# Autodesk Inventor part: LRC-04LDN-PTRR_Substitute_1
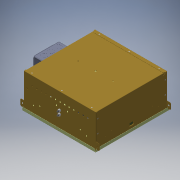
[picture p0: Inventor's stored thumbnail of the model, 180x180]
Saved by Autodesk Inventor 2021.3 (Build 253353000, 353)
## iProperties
Part Number: LRC-04LDN-PTRR_Substitute_1
Material: Generic
Document SubType Name: Modeling
Designer: JChurch
Manufacturer: Standard
Standards Organization: Custom
Density: 1 g/cm^3
Appearance: Smooth - Black
Author: JChurch
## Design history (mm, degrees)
derived "LRC-04LDN-PTRR.iam"
body "Solid9"
node "830520-00-00.ipt:1"
node "881088-00-00.iam:1::830140-00-00.ipt:1"
body "Solid10"
node "881088-00-00.iam:1::850014-00-00.iam:1::805044-00-00.ipt:1"
body "Solid11"
node "881088-00-00.iam:1::850014-00-00.iam:1::805174-00-00.ipt:1"
body "Solid12"
node "881088-00-00.iam:1::850014-00-00.iam:1::502055-00-00.ipt:1"
body "Solid13"
node "881088-00-00.iam:1::850014-00-00.iam:1::502055-00-00.ipt:2"
body "Solid14"
node "881088-00-00.iam:1::850014-00-00.iam:1::507032-00-00.ipt:1"
body "Solid15"
node "881088-00-00.iam:1::507000-00-00.ipt:1"
body "Solid16"
node "881088-00-00.iam:1::507000-00-00.ipt:2"
body "Solid17"
node "881088-00-00.iam:1::506002-00-00.ipt:1"
body "Solid18"
node "881088-00-00.iam:1::506002-00-00.ipt:2"
body "Solid19"
node "881088-00-00.iam:1::506002-00-00.ipt:3"
body "Solid20"
node "881088-00-00.iam:1::506002-00-00.ipt:4"
body "Solid21"
node "881088-00-00.iam:1::506002-00-00.ipt:5"
body "Solid22"
node "881088-00-00.iam:1::506002-00-00.ipt:6"
body "Solid23"
node "881088-00-00.iam:1::506002-00-00.ipt:7"
body "Solid24"
node "881088-00-00.iam:1::506002-00-00.ipt:8"
body "Solid25"
node "881088-00-00.iam:1::506002-00-00.ipt:9"
body "Solid26"
node "881088-00-00.iam:1::506002-00-00.ipt:10"
body "Solid27"
node "881088-00-00.iam:1::506002-00-00.ipt:11"
body "Solid28"
node "881088-00-00.iam:1::506002-00-00.ipt:12"
body "Solid29"
node "881088-00-00.iam:1::506002-00-00.ipt:13"
body "Solid30"
node "881088-00-00.iam:1::506002-00-00.ipt:14"
body "Solid31"
node "881088-00-00.iam:1::830392-01-00.iam:1::830392-00-00.ipt:1"
body "Solid32"
node "881088-00-00.iam:1::830392-01-00.iam:1::500027-00-00.ipt:1"
body "Solid33"
node "881088-00-00.iam:1::830392-01-00.iam:1::501030-00-00.ipt:1"
body "Solid34"
node "881088-00-00.iam:1::830392-01-00.iam:1::500027-00-00.ipt:2"
body "Solid35"
node "881088-00-00.iam:1::830392-01-00.iam:1::501030-00-00.ipt:2"
body "Solid36"
node "881088-00-00.iam:1::830392-01-00.iam:1::501030-00-00.ipt:3"
body "Solid37"
node "881088-00-00.iam:1::830392-01-00.iam:1::501030-00-00.ipt:4"
body "Solid38"
node "881088-00-00.iam:1::830392-01-00.iam:2::830392-00-00.ipt:1"
body "Solid39"
node "881088-00-00.iam:1::830392-01-00.iam:2::500027-00-00.ipt:1"
body "Solid40"
node "881088-00-00.iam:1::830392-01-00.iam:2::501030-00-00.ipt:1"
body "Solid41"
node "881088-00-00.iam:1::830392-01-00.iam:2::500027-00-00.ipt:2"
body "Solid42"
node "881088-00-00.iam:1::830392-01-00.iam:2::501030-00-00.ipt:2"
body "Solid43"
node "881088-00-00.iam:1::830392-01-00.iam:2::501030-00-00.ipt:3"
body "Solid44"
node "881088-00-00.iam:1::830392-01-00.iam:2::501030-00-00.ipt:4"
body "Solid45"
node "750472-00-00.iam:1::740103-00-00.ipt:1"
body "Solid46"
node "750472-00-00.iam:1::507035-01-38.ipt:1"
body "Solid47"
node "750472-00-00.iam:1::507035-01-38.ipt:2"
body "Solid48"
node "750472-00-00.iam:1::502060-00-00.ipt:1"
body "Solid49"
node "750472-00-00.iam:1::510051-00-00.ipt:1"
body "Solid50"
node "750472-00-00.iam:1::502060-00-00.ipt:2"
body "Solid51"
node "750472-00-00.iam:1::502060-00-00.ipt:3"
body "Solid52"
node "750472-00-00.iam:1::502060-00-00.ipt:4"
body "Solid53"
node "725383-01-00.ipt:1"
body "Solid54"
other parameters: "d15" = 61.595, "d16" = 9.525, "d17" = 9.525, "d35" = 5.08
